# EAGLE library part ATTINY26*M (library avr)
MICROCONTROLLER 2 Kbytes FLASH 128 bytes SRAM 128 bytes EEPROM USI 10-channel 10 bit ADC
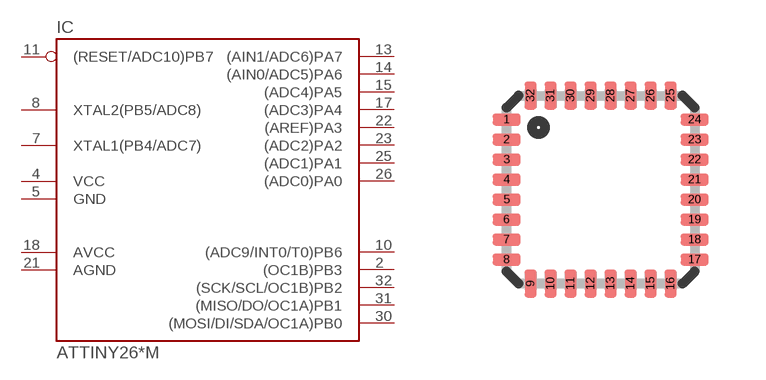
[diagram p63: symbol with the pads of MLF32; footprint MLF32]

Designator prefix IC

## ATTINY26-16M, ATTINY26L-8M  [MLF32]
1  P$1  nc
2  (OC1B)PB3
3  P$2  nc
4  VCC  pwr
5  GND  pwr
6  P$3  nc
7  XTAL1(PB4/ADC7)
8  XTAL2(PB5/ADC8)
9  P$4  nc
10  (ADC9/INT0/T0)PB6
11  (RESET/ADC10)PB7
12  P$5  nc
13  (AIN1/ADC6)PA7
14  (AIN0/ADC5)PA6
15  (ADC4)PA5
16  P$6  nc
17  (ADC3)PA4
18  AVCC  pwr
19  P$7  nc
20  P$8  nc
21  AGND  pwr
22  (AREF)PA3
23  (ADC2)PA2
24  P$9  nc
25  (ADC1)PA1
26  (ADC0)PA0
27  P$10  nc
28  P$11  nc
29  P$12  nc
30  (MOSI/DI/SDA/OC1A)PB0
31  (MISO/DO/OC1A)PB1
32  (SCK/SCL/OC1B)PB2

## Footprint MLF32 (pad centres in mm)
32M1-A Micro Lead Frame package (MLF)
smd 0.7 x 0.3: 1 -2.35,1.75; 2 -2.35,1.25; 3 -2.35,0.75; 4 -2.35,0.25; 5 -2.35,-0.25; 6 -2.35,-0.75; 7 -2.35,-1.25; 8 -2.35,-1.75; 17 2.35,-1.75; 18 2.35,-1.25; 19 2.35,-0.75; 20 2.35,-0.25; 21 2.35,0.25; 22 2.35,0.75; 23 2.35,1.25; 24 2.35,1.75
smd 0.3 x 0.7: 9 -1.75,-2.35; 10 -1.25,-2.35; 11 -0.75,-2.35; 12 -0.25,-2.35; 13 0.25,-2.35; 14 0.75,-2.35; 15 1.25,-2.35; 16 1.75,-2.35; 25 1.75,2.35; 26 1.25,2.35; 27 0.75,2.35; 28 0.25,2.35; 29 -0.25,2.35; 30 -0.75,2.35; 31 -1.25,2.35; 32 -1.75,2.35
